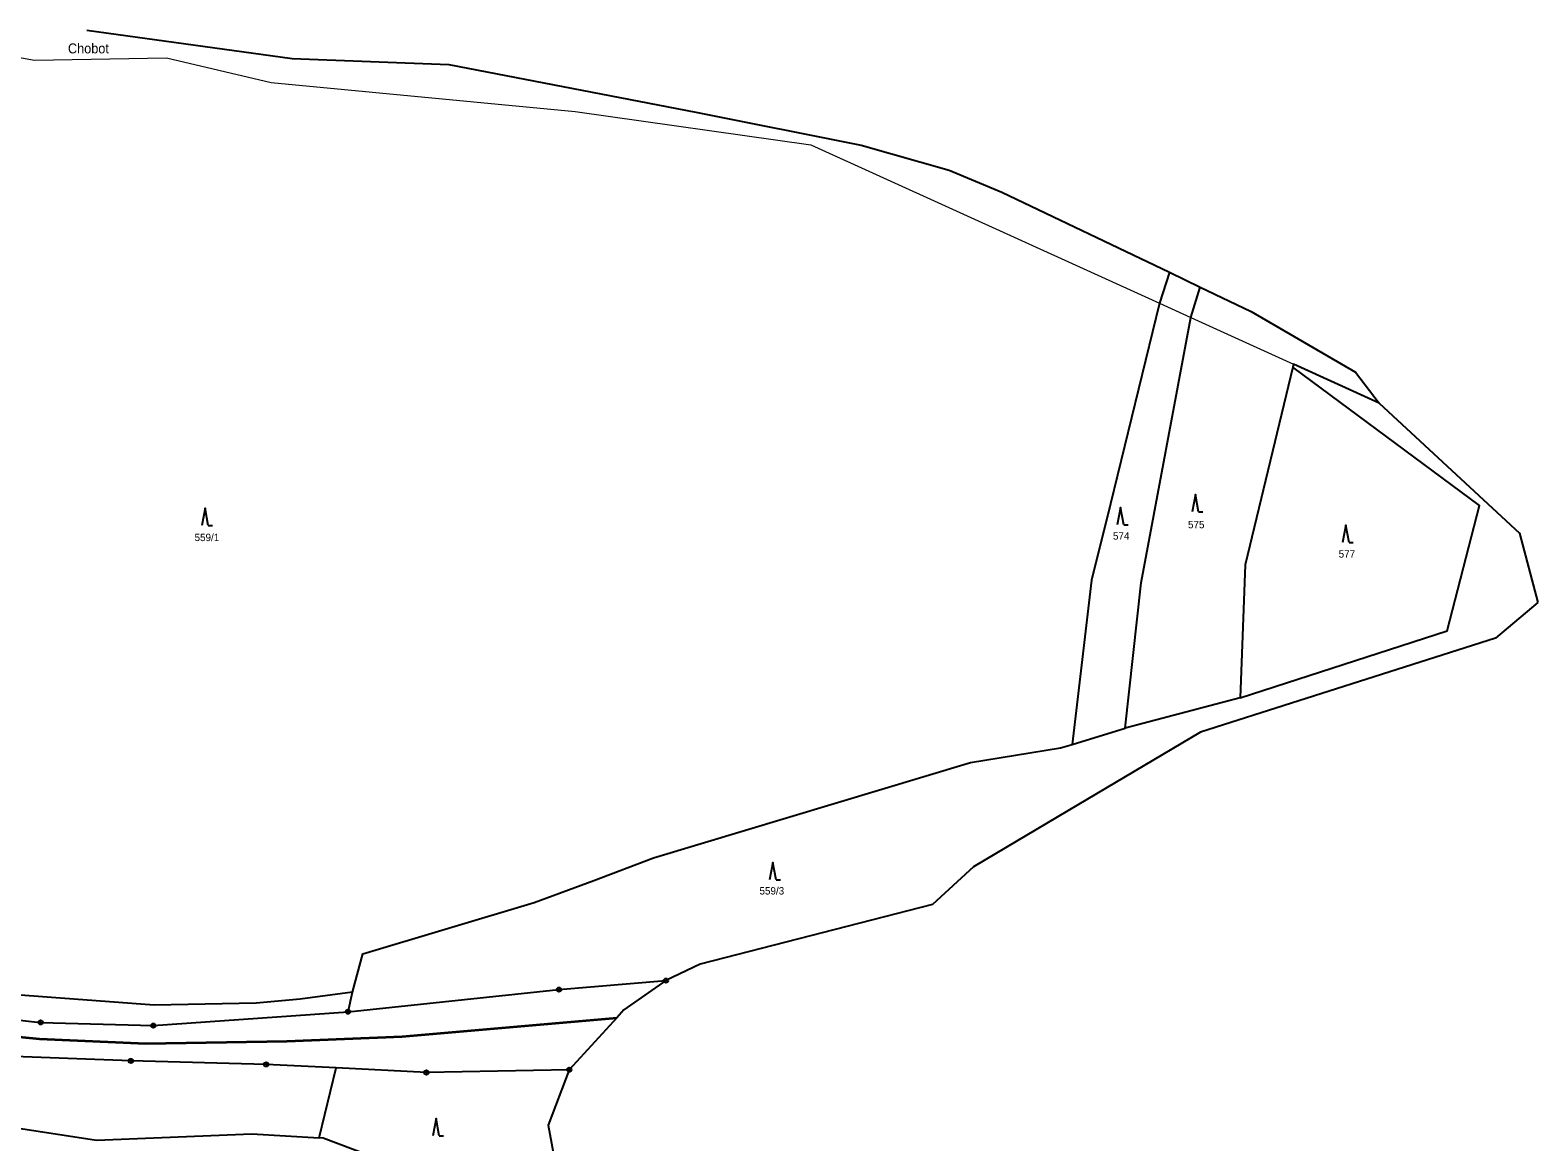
# Model space of a CAD drawing. Extents: x -872229 to -869198, y -1075981 to -1074329.
# Drawn here: x -869544.8 to -869197.7, y -1075466.2 to -1075210.2 of the extents above; entities that cross this region are included whole.
import ezdxf
from ezdxf.enums import TextEntityAlignment as Align

# ---------------------------------------------------------------- set-up
doc = ezdxf.new("R2010")
doc.units = 0
doc.header["$LTSCALE"] = 0.68
for name, color, linetype, lineweight in [('1', 7, 'Continuous', 25), ('3', 7, 'Continuous', 25), ('4', 7, 'Continuous', 13), ('6', 7, 'Continuous', 25), ('7', 7, 'Continuous', 13), ('8', 7, 'Continuous', 25)]:
    doc.layers.add(name, color=color, linetype=linetype, lineweight=lineweight)
doc.layers.add('2', color=7, linetype='Continuous')

msp = doc.modelspace()

# ---------------------------------------------------------------- linework, layer by layer
at = {"layer": '1'}
for p, q in [((-869266.25, -1075363.99), (-869292.73, -1075370.98)), ((-869398.45, -1075429.07), (-869408.14, -1075435.84)), ((-869478.29, -1075465.32), (-869474.41, -1075449.19))]:
    msp.add_line(p, q, dxfattribs=at)
for points in [[(-869531.81, -1075210.17), (-869484.54, -1075216.74), (-869448.42, -1075218.1), (-869391.54, -1075229.06)], [(-869391.54, -1075229.06), (-869353.52, -1075236.64), (-869333.23, -1075242.46), (-869321.07, -1075247.48), (-869282.53, -1075265.95), (-869275.45, -1075269.34)], [(-869282.53, -1075265.95), (-869284.79, -1075273.08), (-869296.06, -1075319.3), (-869300.48, -1075336.87), (-869304.9, -1075374.68), (-869292.73, -1075370.98)], [(-869292.73, -1075370.98), (-869289.05, -1075337.45), (-869277.59, -1075276.36), (-869275.45, -1075269.34)], [(-869275.45, -1075269.34), (-869263.72, -1075274.96), (-869239.64, -1075288.97), (-869234.22, -1075296.09), (-869201.89, -1075326.03), (-869197.69, -1075342.02)], [(-869266.25, -1075363.99), (-869218.58, -1075348.55), (-869211.15, -1075319.68), (-869254.14, -1075287.83)], [(-869254.14, -1075287.83), (-869265.05, -1075333.33), (-869266.25, -1075363.99)], [(-869234.22, -1075296.09), (-869253.97, -1075287.1), (-869254.14, -1075287.83)], [(-869197.69, -1075342.02), (-869207.41, -1075350.18), (-869275.36, -1075371.88), (-869305.91, -1075389.99), (-869327.65, -1075402.88), (-869337.06, -1075411.58)], [(-869470.63, -1075431.72), (-869468.23, -1075422.93), (-869428.75, -1075411.1), (-869415.02, -1075406.03), (-869401.31, -1075400.81), (-869328.31, -1075378.82), (-869307.57, -1075375.49), (-869304.9, -1075374.68)], [(-869470.63, -1075431.72), (-869482.67, -1075433.38), (-869492.77, -1075434.3), (-869516.25, -1075434.78), (-869548.16, -1075432.33), (-869575.31, -1075429.18), (-869592.79, -1075426.68), (-869627.42, -1075419.15), (-869656.02, -1075410.53), (-869671.66, -1075407.34), (-869676.3, -1075404.74)], [(-869682.1, -1075410.63), (-869678.59, -1075410.32), (-869671.56, -1075413.43), (-869624.66, -1075426.43), (-869585.55, -1075433.9), (-869542.43, -1075438.72), (-869516.5, -1075439.44), (-869471.65, -1075436.24), (-869470.63, -1075431.72)], [(-869337.06, -1075411.58), (-869390.53, -1075425.32), (-869398.45, -1075429.07)], [(-869474.41, -1075449.19), (-869490.49, -1075448.38), (-869521.65, -1075447.59), (-869552.7, -1075446.43), (-869583.47, -1075442.4), (-869614.13, -1075437.41), (-869643.97, -1075429.64), (-869680.93, -1075420.53), (-869682.99, -1075432.01), (-869660.1, -1075439.54)], [(-869471.65, -1075436.24), (-869423.07, -1075431.15), (-869398.45, -1075429.07)], [(-869408.14, -1075435.84), (-869409.77, -1075437.63), (-869420.7, -1075449.61)], [(-869660.1, -1075439.54), (-869639.17, -1075443.87), (-869615.03, -1075449.51), (-869552.02, -1075462.41), (-869529.57, -1075465.84), (-869493.81, -1075464.4), (-869478.29, -1075465.32)], [(-869420.7, -1075449.61), (-869453.61, -1075450.25), (-869474.41, -1075449.19)], [(-869420.7, -1075449.61), (-869425.54, -1075462.39), (-869421.29, -1075485.67)], [(-869421.29, -1075485.67), (-869434.21, -1075480.71), (-869445.65, -1075477.37), (-869477.35, -1075465.38), (-869478.29, -1075465.32)]]:
    msp.add_lwpolyline(points, dxfattribs=at)
at = {"layer": '3'}
for p, q in [((-869275.8, -1075321.15), (-869274.804, -1075321.15)), ((-869503.82, -1075324.24), (-869502.824, -1075324.24)), ((-869293.02, -1075324.12), (-869292.024, -1075324.12)), ((-869241.17, -1075328.18), (-869240.174, -1075328.18)), ((-869373.08, -1075405.88), (-869372.084, -1075405.88)), ((-869450.63, -1075464.81), (-869449.634, -1075464.81))]:
    msp.add_line(p, q, dxfattribs=at)
for points in [[(-869275.8, -1075321.15), (-869276.55, -1075317.15), (-869277.3, -1075321.15)], [(-869503.82, -1075324.24), (-869504.57, -1075320.24), (-869505.32, -1075324.24)], [(-869293.02, -1075324.12), (-869293.77, -1075320.12), (-869294.52, -1075324.12)], [(-869241.17, -1075328.18), (-869241.92, -1075324.18), (-869242.67, -1075328.18)], [(-869373.08, -1075405.88), (-869373.83, -1075401.88), (-869374.58, -1075405.88)], [(-869450.63, -1075464.81), (-869451.38, -1075460.81), (-869452.13, -1075464.81)]]:
    msp.add_lwpolyline(points, dxfattribs=at)
at = {"layer": '4'}
msp.add_line((-869583.06, -1075210.18), (-869543.86, -1075217.07), dxfattribs=at)
msp.add_lwpolyline([(-869543.86, -1075217.07), (-869513.42, -1075216.57), (-869489.36, -1075222.2), (-869419.31, -1075228.93), (-869365.07, -1075236.56), (-869284.79, -1075273.08), (-869277.59, -1075276.36), (-869253.97, -1075287.1)], dxfattribs=at)
at = {"layer": '6', "lineweight": 35}
msp.add_lwpolyline([(-869860.88, -1075365.74), (-869846.01, -1075369.94), (-869704.43, -1075408.78), (-869641.66, -1075426.07), (-869625.84, -1075430.18), (-869607.72, -1075434.15), (-869580.2, -1075438.82), (-869542.66, -1075442.5), (-869518.18, -1075443.57), (-869485.71, -1075443.04), (-869459.17, -1075441.98), (-869409.77, -1075437.63)], dxfattribs=at)
at = {"layer": '8'}
for centre, radius in [((-869423.07, -1075431.1499), 0.5), ((-869398.45, -1075429.0699), 0.5), ((-869398.45, -1075429.0699), 0.0303), ((-869423.07, -1075431.1499), 0.0303), ((-869471.65, -1075436.2399), 0.5), ((-869471.65, -1075436.2399), 0.0303), ((-869542.43, -1075438.7199), 0.5), ((-869542.43, -1075438.7199), 0.0303), ((-869516.5, -1075439.4399), 0.5), ((-869516.5, -1075439.4399), 0.0303), ((-869521.65, -1075447.5899), 0.5), ((-869521.65, -1075447.5899), 0.0303), ((-869490.49, -1075448.3799), 0.5), ((-869490.49, -1075448.3799), 0.0303), ((-869453.61, -1075450.2499), 0.5), ((-869453.61, -1075450.2499), 0.0303), ((-869420.7, -1075449.6099), 0.5), ((-869420.7, -1075449.6099), 0.0303)]:
    msp.add_circle(centre, radius, dxfattribs=at)

# ---------------------------------------------------------------- texts
at = {"layer": '2'}
for s, p in [('575', (-869278.24, -1075324.9)), ('559/1', (-869506.98, -1075327.86)), ('574', (-869295.52, -1075327.52)), ('577', (-869243.55, -1075331.66)), ('559/3', (-869376.91, -1075409.26))]:
    msp.add_text(s, height=1.7, dxfattribs=at).set_placement(p)
at = {"layer": '7', "width": 0.95}
msp.add_text('Chobot', height=2.3, dxfattribs=at).set_placement((-869531.419, -1075215.53), align=Align.CENTER)

doc.saveas('drawing.dxf')
